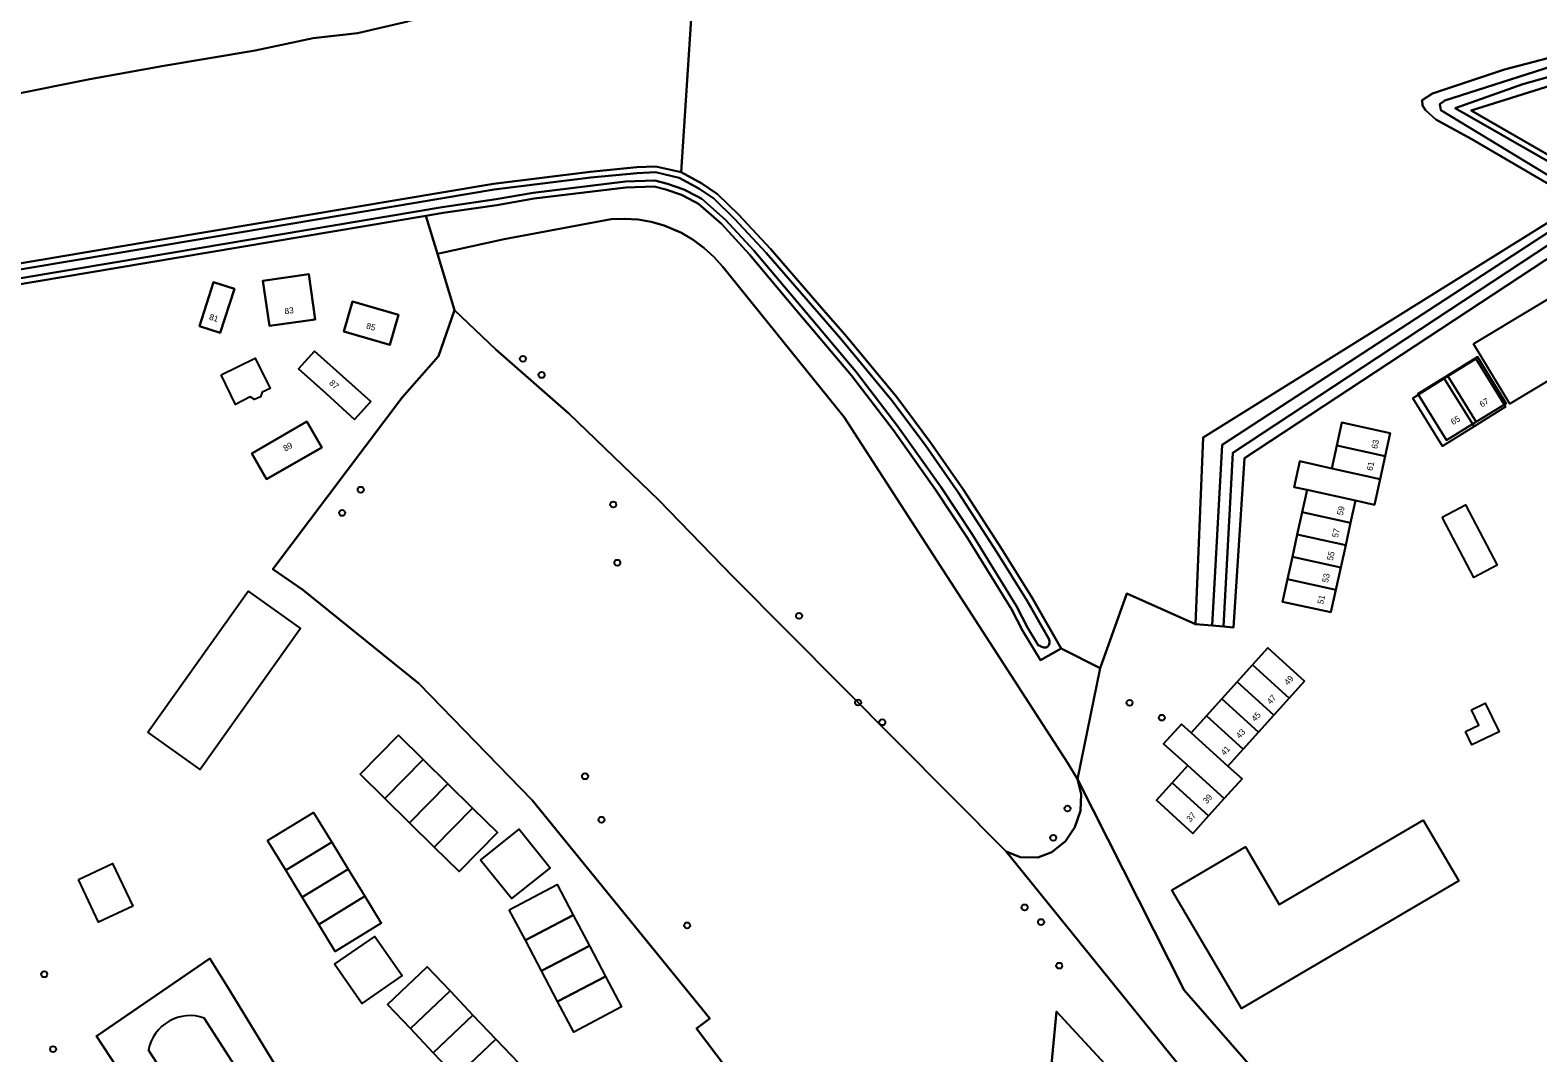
# Model space of a CAD drawing. Extents: x 159451 to 160664, y 388402 to 389723.
# Drawn here: x 159623.4 to 159869.7, y 389378.7 to 389545.7 of the extents above; entities that cross this region are included whole.
import ezdxf

# ---------------------------------------------------------------- set-up
doc = ezdxf.new("R2010")
doc.units = 0
for name, color, linetype in [('IMGEO_Boom', 7, 'Continuous'), ('IMGEO_Greppel_droge_sloot', 7, 'Continuous'), ('IMGEO_Groenvoorziening', 7, 'Continuous'), ('IMGEO_Loofbos', 7, 'Continuous'), ('IMGEO_Oever', 7, 'Continuous'), ('IMGEO_Pand', 7, 'Continuous'), ('IMGEO_Pand_nummerreeks', 7, 'Continuous'), ('IMGEO_Pand_vergunning_verleend', 7, 'Continuous'), ('IMGEO_Rijbaan_lokaal_gesloten', 7, 'Continuous'), ('IMGEO_Waterloop', 7, 'Continuous')]:
    doc.layers.add(name, color=color, linetype=linetype)

msp = doc.modelspace()

# ---------------------------------------------------------------- linework, layer by layer
at = {"layer": 'IMGEO_Boom'}
for centre in [(159703.89, 389492.02), (159706.95, 389489.4), (159677.39, 389470.65), (159674.37, 389466.85), (159718.65, 389468.24), (159719.32, 389458.72), (159749.01, 389450.04), (159758.65, 389435.9), (159803, 389435.84), (159762.6, 389432.66), (159808.28, 389433.41), (159714.04, 389423.83), (159792.86, 389418.57), (159716.73, 389416.74), (159790.53, 389413.78), (159785.86, 389402.42), (159788.54, 389400.03), (159730.73, 389399.48), (159791.51, 389392.9), (159625.69, 389391.49), (159627.14, 389379.27)]:
    msp.add_circle(centre, 0.489, dxfattribs=at)
at = {"layer": 'IMGEO_Greppel_droge_sloot'}
msp.add_lwpolyline([(159596.51, 389500.94), (159637.44, 389507.84), (159690.69, 389516.8), (159699.51, 389518.1), (159705.57, 389519.14), (159720.65, 389521), (159725.44, 389521.13), (159727.53, 389520.63), (159730.19, 389519.71), (159732.43, 389518.52), (159733.15, 389518.14), (159737, 389514.75), (159741.64, 389509.7), (159749.29, 389500.62), (159758.3, 389489.93), (159765.13, 389480.99), (159772.16, 389471.12), (159777.29, 389463.37), (159784.54, 389451.63), (159786.35, 389448.14), (159788.06, 389445.28), (159788.36, 389445.12), (159788.69, 389444.97), (159789, 389444.87), (159789.39, 389444.87), (159789.65, 389445.01), (159789.84, 389445.23), (159789.93, 389445.59), (159789.9, 389445.94), (159789.82, 389446.3), (159786.26, 389452.47), (159781.32, 389460.44), (159775.05, 389470.11), (159769.72, 389477.79), (159764.23, 389485.16), (159755.83, 389495.32), (159752.3, 389499.37), (159743.62, 389509.35), (159738.45, 389514.92), (159735.08, 389518.19), (159732.63, 389519.84), (159729.4, 389521.61), (159725.54, 389522.51), (159722.58, 389522.36), (159715, 389521.63), (159699.21, 389519.66), (159636.97, 389509.2), (159576.64, 389499.06)], dxfattribs=at)
at = {"layer": 'IMGEO_Groenvoorziening'}
for points in [[(159731.83, 389554.33), (159729.75, 389522.51), (159733.13, 389520.66), (159735.68, 389518.93), (159739.14, 389515.59), (159744.33, 389509.98), (159753.02, 389500), (159756.56, 389495.94), (159764.98, 389485.75), (159770.49, 389478.35), (159775.85, 389470.64), (159782.12, 389460.95), (159787.08, 389452.96), (159791.82, 389444.73), (159798.18, 389441.51), (159802.55, 389453.69), (159813.75, 389448.69), (159815.03, 389479.17), (159876.64, 389517.57), (159858.8, 389527.98), (159853.01, 389531.14), (159851.33, 389532.64), (159850.85, 389533.41), (159850.81, 389534.29), (159852.5, 389535.39), (159864.26, 389539.27), (159877.37, 389542.72)], [(159881.2, 389539.62), (159858.79, 389532.6), (159882.61, 389518.89)], [(159762.21, 389343.03), (159732.27, 389382.65), (159734.43, 389384.27), (159705.43, 389419.91), (159686.88, 389439.01), (159667.95, 389454.31), (159663.03, 389457.69), (159684.18, 389485.7), (159690.1, 389492.47), (159692.72, 389500), (159689.92, 389509.16), (159688.02, 389515.39), (159637.6, 389506.89), (159598.51, 389500.31), (159596.13, 389493.71), (159594.28, 389488.58), (159590.7, 389478.95), (159585.18, 389466.83), (159566.64, 389445.47), (159556.46, 389431.12), (159544.81, 389411.57), (159514.87, 389357.94)], [(159881.7, 389515.21), (159821.76, 389475.8), (159819.99, 389448.16), (159818.33, 389448.3), (159816.5, 389448.46), (159813.75, 389448.69), (159802.55, 389453.69), (159798.18, 389441.51), (159794.48, 389423.34), (159811.91, 389388.9), (159831.1, 389366.95)], [(159656.13, 389347.78), (159637.53, 389376.31), (159634.21, 389381.4), (159652.75, 389394.08), (159655.46, 389389.69), (159680.67, 389348.37), (159655.34, 389331.64), (159623.74, 389311.39)], [(159816.71, 389357.62), (159791.04, 389385.41), (159788.61, 389359.57)], [(159670.77, 389354.89), (159651.84, 389384.35)], [(159642.74, 389379.11), (159662.42, 389348.77)]]:
    msp.add_lwpolyline(points, dxfattribs=at)
for points in [[(159756.38, 389482.5), (159792.91, 389425.98), (159794.48, 389423.34), (159798.18, 389441.51), (159791.82, 389444.73), (159788.43, 389442.8), (159785.52, 389447.67), (159783.71, 389451.16), (159776.49, 389462.85), (159771.37, 389470.58), (159764.36, 389480.42), (159757.55, 389489.33), (159748.56, 389500), (159740.92, 389509.07), (159736.33, 389514.06), (159732.6, 389517.34), (159731.98, 389517.67), (159729.81, 389518.83), (159727.26, 389519.71), (159725.34, 389520.17), (159720.72, 389520.04), (159705.71, 389518.19), (159699.66, 389517.15), (159690.84, 389515.86), (159688.02, 389515.39), (159689.92, 389509.16), (159700.83, 389511.58), (159718.3, 389514.83), (159720.5, 389514.91), (159722.7, 389514.76), (159724.87, 389514.38), (159726.99, 389513.78), (159729.79, 389512.59), (159731.69, 389511.48), (159733.47, 389510.18), (159735.11, 389508.7), (159736.57, 389507.05)], [(159651.07, 389497.37), (159653.36, 389504.57), (159656.75, 389503.46), (159654.46, 389496.28)], [(159662.49, 389497.41), (159661.43, 389504.79), (159668.91, 389505.84), (159669.93, 389498.47)], [(159674.62, 389496.47), (159676.03, 389501.38), (159683.58, 389499.21), (159682.17, 389494.31)], [(159667.25, 389490.37), (159669.85, 389493.27), (159679.04, 389485.08), (159676.39, 389482.14), (159671.73, 389486.34)], [(159854.77, 389478.73), (159850.07, 389486.32), (159854.95, 389489.33), (159859.82, 389492.33), (159864.51, 389484.74), (159859.64, 389481.74)], [(159662.01, 389472.37), (159659.59, 389476.58), (159668.61, 389481.77), (159671.03, 389477.56)], [(159835.89, 389450.62), (159827.99, 389452.35), (159828.8, 389456.02), (159829.6, 389459.67), (159830.41, 389463.32), (159831.22, 389466.97), (159832.02, 389470.6), (159829.89, 389471.07), (159830.84, 389475.29), (159836.03, 389474.13), (159836.86, 389477.88), (159837.68, 389481.63), (159845.58, 389479.88), (159844.76, 389476.14), (159843.92, 389472.38), (159843, 389468.19), (159839.93, 389468.87), (159839.12, 389465.22), (159838.31, 389461.57), (159837.51, 389457.92), (159836.7, 389454.27)], [(159821.39, 389423.4), (159818.48, 389420.18), (159815.91, 389417.35), (159813.35, 389414.51), (159807.38, 389419.91), (159809.94, 389422.74), (159812.5, 389425.58), (159808.56, 389429.15), (159811.46, 389432.36), (159813.06, 389430.92), (159815.57, 389433.7), (159818.08, 389436.47), (159820.58, 389439.25), (159823.08, 389442.02), (159825.6, 389444.8), (159831.59, 389439.38), (159829.08, 389436.6), (159826.58, 389433.83), (159824.07, 389431.06), (159821.56, 389428.28), (159819.06, 389425.51)]]:
    msp.add_lwpolyline(points, close=True, dxfattribs=at)
msp.add_arc((159649.52, 389377.85), 6.9, 70.344, 169.5205, dxfattribs=at)
at = {"layer": 'IMGEO_Loofbos'}
for points in [[(159576.46, 389500), (159636.81, 389510.14), (159699.07, 389520.6), (159714.9, 389522.58), (159722.51, 389523.32), (159725.62, 389523.47), (159729.75, 389522.51), (159731.83, 389554.33), (159731.08, 389555.64), (159724.67, 389554.6), (159718.89, 389553.47), (159712.88, 389552.12), (159706.72, 389550.96), (159698.42, 389549.8), (159691.08, 389548.68), (159685.11, 389547.14), (159676.86, 389545.24), (159669.65, 389544.38), (159660.15, 389542.41), (159645.22, 389539.91), (159633.12, 389537.69), (159620.1, 389535.12)], [(159620.1, 389535.12), (159633.12, 389537.69), (159645.22, 389539.91), (159660.15, 389542.41), (159669.65, 389544.38), (159676.86, 389545.24), (159685.11, 389547.14)], [(159827.32, 389356.54), (159782.84, 389411.56), (159738.22, 389456.43), (159726.07, 389468.98), (159711.41, 389483.1), (159699.45, 389493.54), (159692.72, 389500), (159690.1, 389492.47), (159684.18, 389485.7), (159663.03, 389457.69), (159667.95, 389454.31), (159686.88, 389439.01), (159705.43, 389419.91), (159734.43, 389384.27), (159732.27, 389382.65), (159762.21, 389343.03)], [(159788.61, 389359.57), (159791.04, 389385.41), (159816.71, 389357.62)]]:
    msp.add_lwpolyline(points, dxfattribs=at)
for points in [[(159756.38, 389482.5), (159736.57, 389507.05), (159735.11, 389508.7), (159733.47, 389510.18), (159731.69, 389511.48), (159729.79, 389512.59), (159726.99, 389513.78), (159724.87, 389514.38), (159722.7, 389514.76), (159720.5, 389514.91), (159718.3, 389514.83), (159700.83, 389511.58), (159689.92, 389509.16), (159692.72, 389500), (159699.45, 389493.54), (159711.41, 389483.1), (159726.07, 389468.98), (159738.22, 389456.43), (159782.84, 389411.56), (159785.15, 389410.62), (159788, 389410.57), (159790.3, 389411.43), (159792.55, 389413.25), (159794.05, 389415.51), (159794.97, 389418.19), (159795.07, 389420.92), (159794.48, 389423.34), (159792.91, 389425.98)], [(159831.1, 389366.95), (159811.91, 389388.9), (159794.48, 389423.34), (159795.07, 389420.92), (159794.97, 389418.19), (159794.05, 389415.51), (159792.55, 389413.25), (159790.3, 389411.43), (159788, 389410.57), (159785.15, 389410.62), (159782.84, 389411.56), (159827.32, 389356.54), (159838.14, 389339.9), (159876.34, 389281.17), (159877.68, 389282.04), (159881.39, 389288.32), (159874.34, 389299.54), (159850.68, 389337.23)]]:
    msp.add_lwpolyline(points, close=True, dxfattribs=at)
at = {"layer": 'IMGEO_Oever'}
for points in [[(159877.37, 389542.72), (159864.26, 389539.27), (159852.5, 389535.39), (159850.81, 389534.29), (159850.85, 389533.41), (159851.33, 389532.64), (159853.01, 389531.14), (159858.8, 389527.98), (159876.64, 389517.57), (159815.03, 389479.17), (159813.75, 389448.69), (159816.5, 389448.46), (159818.15, 389477.97), (159878.82, 389517.52), (159853.88, 389532.62), (159853.68, 389533.62), (159854.53, 389534.2), (159877.32, 389541.54)], [(159881.02, 389540.75), (159867.27, 389536.87), (159856.18, 389532.97), (159881.4, 389518.55)], [(159882.61, 389518.89), (159858.79, 389532.6), (159881.2, 389539.62)], [(159598.51, 389500.31), (159637.6, 389506.89), (159688.02, 389515.39), (159690.84, 389515.86), (159699.66, 389517.15), (159705.71, 389518.19), (159720.72, 389520.04), (159725.34, 389520.17), (159727.26, 389519.71), (159729.81, 389518.83), (159731.98, 389517.67), (159732.6, 389517.34), (159736.33, 389514.06), (159740.92, 389509.07), (159748.56, 389500), (159757.55, 389489.33), (159764.36, 389480.42), (159771.37, 389470.58), (159776.49, 389462.85), (159783.71, 389451.16), (159785.52, 389447.67), (159788.43, 389442.8), (159791.82, 389444.73), (159787.08, 389452.96), (159782.12, 389460.95), (159775.85, 389470.64), (159770.49, 389478.35), (159764.98, 389485.75), (159756.56, 389495.94), (159753.02, 389500), (159744.33, 389509.98), (159739.14, 389515.59), (159735.68, 389518.93), (159733.13, 389520.66), (159729.75, 389522.51), (159725.62, 389523.47), (159722.51, 389523.32), (159714.9, 389522.58), (159699.07, 389520.6), (159636.81, 389510.14), (159576.46, 389500)], [(159576.64, 389499.06), (159636.97, 389509.2), (159699.21, 389519.66), (159715, 389521.63), (159722.58, 389522.36), (159725.54, 389522.51), (159729.4, 389521.61), (159732.63, 389519.84), (159735.08, 389518.19), (159738.45, 389514.92), (159743.62, 389509.35), (159752.3, 389499.37), (159755.83, 389495.32), (159764.23, 389485.16), (159769.72, 389477.79), (159775.05, 389470.11), (159781.32, 389460.44), (159786.26, 389452.47), (159789.82, 389446.3), (159789.9, 389445.94), (159789.93, 389445.59), (159789.84, 389445.23), (159789.65, 389445.01), (159789.39, 389444.87), (159789, 389444.87), (159788.69, 389444.97), (159788.36, 389445.12), (159788.06, 389445.28), (159786.35, 389448.14), (159784.54, 389451.63), (159777.29, 389463.37), (159772.16, 389471.12), (159765.13, 389480.99), (159758.3, 389489.93), (159749.29, 389500.62), (159741.64, 389509.7), (159737, 389514.75), (159733.15, 389518.14), (159732.43, 389518.52), (159730.19, 389519.71), (159727.53, 389520.63), (159725.44, 389521.13), (159720.65, 389521), (159705.57, 389519.14), (159699.51, 389518.1), (159690.69, 389516.8), (159637.44, 389507.84), (159596.51, 389500.94)], [(159881.21, 389517.06), (159819.88, 389476.66), (159818.33, 389448.3), (159819.99, 389448.16), (159821.76, 389475.8), (159881.7, 389515.21)]]:
    msp.add_lwpolyline(points, dxfattribs=at)
at = {"layer": 'IMGEO_Pand'}
for points in [[(159656.75, 389503.46), (159653.36, 389504.57), (159651.07, 389497.37), (159654.46, 389496.28)], [(159668.91, 389505.84), (159661.43, 389504.79), (159662.49, 389497.41), (159669.93, 389498.47)], [(159683.58, 389499.21), (159676.03, 389501.38), (159674.62, 389496.47), (159682.17, 389494.31)], [(159669.85, 389493.27), (159667.25, 389490.37), (159671.73, 389486.34), (159676.39, 389482.14), (159679.04, 389485.08)], [(159859.82, 389492.33), (159854.95, 389489.33), (159859.64, 389481.74), (159864.51, 389484.74)], [(159854.95, 389489.33), (159850.07, 389486.32), (159854.77, 389478.73), (159859.64, 389481.74)], [(159671.03, 389477.56), (159668.61, 389481.77), (159659.59, 389476.58), (159662.01, 389472.37)], [(159845.58, 389479.88), (159837.68, 389481.63), (159836.86, 389477.88), (159844.76, 389476.14)], [(159844.76, 389476.14), (159836.86, 389477.88), (159836.03, 389474.13), (159843.92, 389472.38)], [(159843.92, 389472.38), (159836.03, 389474.13), (159830.84, 389475.29), (159829.89, 389471.07), (159832.02, 389470.6), (159832.02, 389470.61), (159839.93, 389468.87), (159843, 389468.19)], [(159839.93, 389468.87), (159832.02, 389470.61), (159832.02, 389470.6), (159831.22, 389466.97), (159839.12, 389465.22)], [(159839.12, 389465.22), (159831.22, 389466.97), (159830.41, 389463.32), (159838.31, 389461.57)], [(159838.31, 389461.57), (159830.41, 389463.32), (159829.6, 389459.67), (159837.51, 389457.92)], [(159837.51, 389457.92), (159829.6, 389459.67), (159828.8, 389456.02), (159836.7, 389454.27)], [(159836.7, 389454.27), (159828.8, 389456.02), (159827.99, 389452.35), (159835.89, 389450.62)], [(159825.6, 389444.8), (159823.08, 389442.02), (159829.08, 389436.6), (159831.59, 389439.38)], [(159823.08, 389442.02), (159820.58, 389439.25), (159826.58, 389433.83), (159829.08, 389436.6)], [(159820.58, 389439.25), (159818.08, 389436.47), (159824.07, 389431.06), (159826.58, 389433.83)], [(159818.08, 389436.47), (159815.57, 389433.7), (159821.56, 389428.28), (159824.07, 389431.06)], [(159813.06, 389430.92), (159811.46, 389432.36), (159808.56, 389429.15), (159812.5, 389425.58), (159818.48, 389420.18), (159821.39, 389423.4), (159819.06, 389425.51)], [(159815.57, 389433.7), (159813.06, 389430.92), (159819.06, 389425.51), (159821.56, 389428.28)], [(159812.5, 389425.58), (159809.94, 389422.74), (159815.91, 389417.35), (159818.48, 389420.18)], [(159809.94, 389422.74), (159807.38, 389419.91), (159813.35, 389414.51), (159815.91, 389417.35)]]:
    msp.add_lwpolyline(points, close=True, dxfattribs=at)
at = {"layer": 'IMGEO_Pand_vergunning_verleend'}
for points in [[(159859.2, 389494.48), (159879.13, 389506.48), (159890.64, 389487.37), (159881.35, 389481.77), (159875.76, 389491.06), (159865.11, 389484.66)], [(159654.6, 389489.4), (159660.15, 389492.13), (159662.58, 389487.19), (159661.31, 389486.57), (159661.04, 389485.83), (159660.05, 389485.41), (159659.33, 389485.81), (159656.96, 389484.58)], [(159854.42, 389488.82), (159859.57, 389492.01), (159864.43, 389484.18), (159859.28, 389480.98)], [(159849.27, 389485.62), (159854.42, 389488.82), (159859.28, 389480.98), (159854.13, 389477.78)], [(159854.06, 389466.18), (159857.88, 389468.19), (159863.07, 389458.32), (159859.25, 389456.31)], [(159642.63, 389431.05), (159659.02, 389454.05), (159667.55, 389447.96), (159651.16, 389424.96)], [(159857.86, 389431.14), (159860.05, 389432.2), (159858.85, 389434.67), (159861.11, 389435.77), (159863.36, 389431.11), (159858.92, 389428.96)], [(159677.28, 389424.2), (159683.55, 389430.57), (159687.59, 389426.59), (159681.33, 389420.22)], [(159681.33, 389420.22), (159687.59, 389426.59), (159691.64, 389422.61), (159685.37, 389416.24)], [(159685.37, 389416.24), (159691.64, 389422.61), (159695.68, 389418.63), (159689.42, 389412.26)], [(159662.18, 389413.35), (159669.7, 389417.94), (159672.66, 389413.08), (159665.15, 389408.49)], [(159689.42, 389412.26), (159695.68, 389418.63), (159699.73, 389414.65), (159693.46, 389408.28)], [(159696.99, 389410.15), (159703.29, 389415.19), (159708.33, 389408.89), (159702.03, 389403.85)], [(159809.93, 389405.25), (159821.93, 389412.29), (159827.46, 389402.87), (159850.97, 389416.67), (159856.8, 389406.76), (159821.28, 389385.91)], [(159665.15, 389408.49), (159672.66, 389413.08), (159675.36, 389408.66), (159667.84, 389404.07)], [(159631.28, 389406.97), (159636.86, 389409.6), (159640.14, 389402.64), (159634.56, 389400.01)], [(159667.84, 389404.07), (159675.36, 389408.66), (159678.06, 389404.24), (159670.54, 389399.65)], [(159701.66, 389402.04), (159709.48, 389406.16), (159712.11, 389401.16), (159704.3, 389397.04)], [(159670.54, 389399.65), (159678.06, 389404.24), (159680.75, 389399.82), (159673.24, 389395.23)], [(159704.3, 389397.04), (159712.11, 389401.16), (159714.75, 389396.15), (159706.93, 389392.04)], [(159673.14, 389393.12), (159679.71, 389397.69), (159684.15, 389391.3), (159677.59, 389386.73)], [(159706.93, 389392.04), (159714.75, 389396.15), (159717.38, 389391.15), (159709.57, 389387.03)], [(159681.77, 389386.55), (159688.25, 389392.7), (159691.99, 389388.77), (159685.51, 389382.61)], [(159709.57, 389387.03), (159717.38, 389391.15), (159720.02, 389386.15), (159712.2, 389382.03)], [(159685.51, 389382.61), (159691.99, 389388.77), (159695.73, 389384.83), (159689.25, 389378.67)], [(159689.25, 389378.67), (159695.73, 389384.83), (159699.47, 389380.89), (159693, 389374.74)], [(159693, 389374.74), (159699.47, 389380.89), (159703.21, 389376.96), (159696.74, 389370.8)]]:
    msp.add_lwpolyline(points, close=True, dxfattribs=at)
at = {"layer": 'IMGEO_Rijbaan_lokaal_gesloten'}
for points in [[(159623.74, 389311.39), (159655.34, 389331.64), (159680.67, 389348.37), (159655.46, 389389.69), (159652.75, 389394.08), (159634.21, 389381.4), (159637.53, 389376.31)], [(159651.84, 389384.35), (159670.77, 389354.89)], [(159662.42, 389348.77), (159642.74, 389379.11)]]:
    msp.add_lwpolyline(points, dxfattribs=at)
msp.add_arc((159649.52, 389377.85), 6.9, 70.344, 169.5205, dxfattribs=at)
at = {"layer": 'IMGEO_Waterloop'}
for points in [[(159877.32, 389541.54), (159854.53, 389534.2), (159853.68, 389533.62), (159853.88, 389532.62), (159878.82, 389517.52), (159818.15, 389477.97), (159816.5, 389448.46), (159818.33, 389448.3), (159819.88, 389476.66), (159881.21, 389517.06)], [(159881.4, 389518.55), (159856.18, 389532.97), (159867.27, 389536.87), (159881.02, 389540.75)]]:
    msp.add_lwpolyline(points, dxfattribs=at)

# ---------------------------------------------------------------- texts
at = {"layer": 'IMGEO_Pand_nummerreeks'}
for s, rotation, p in [('81', 342.1581, (159652.55, 389498.47)), ('83', 8.0558, (159665.03, 389499.29)), ('85', 344.0259, (159678.22, 389497)), ('87', 318.0194, (159672.17, 389487.96)), ('67', 31.6731, (159860.55, 389484.06)), ('65', 31.6731, (159855.86, 389481.17)), ('89', 29.9199, (159665.09, 389476.86)), ('63', 77.5498, (159843.46, 389477.25)), ('61', 77.5498, (159842.68, 389473.68)), ('59', 77.5384, (159837.84, 389466.38)), ('57', 77.5384, (159837.04, 389462.74)), ('55', 77.5384, (159836.21, 389459)), ('53', 77.5384, (159835.41, 389455.4)), ('51', 77.5384, (159834.64, 389451.88)), ('49', 47.905, (159828.89, 389438.63)), ('47', 47.905, (159826.06, 389435.5)), ('45', 47.905, (159823.53, 389432.7)), ('43', 47.905, (159821.02, 389429.92)), ('41', 47.905, (159818.53, 389427.16)), ('39', 47.8649, (159815.62, 389419.26)), ('37', 47.8649, (159812.93, 389416.29))]:
    msp.add_text(s, height=1, rotation=rotation, dxfattribs=at).set_placement(p)

doc.saveas('drawing.dxf')
